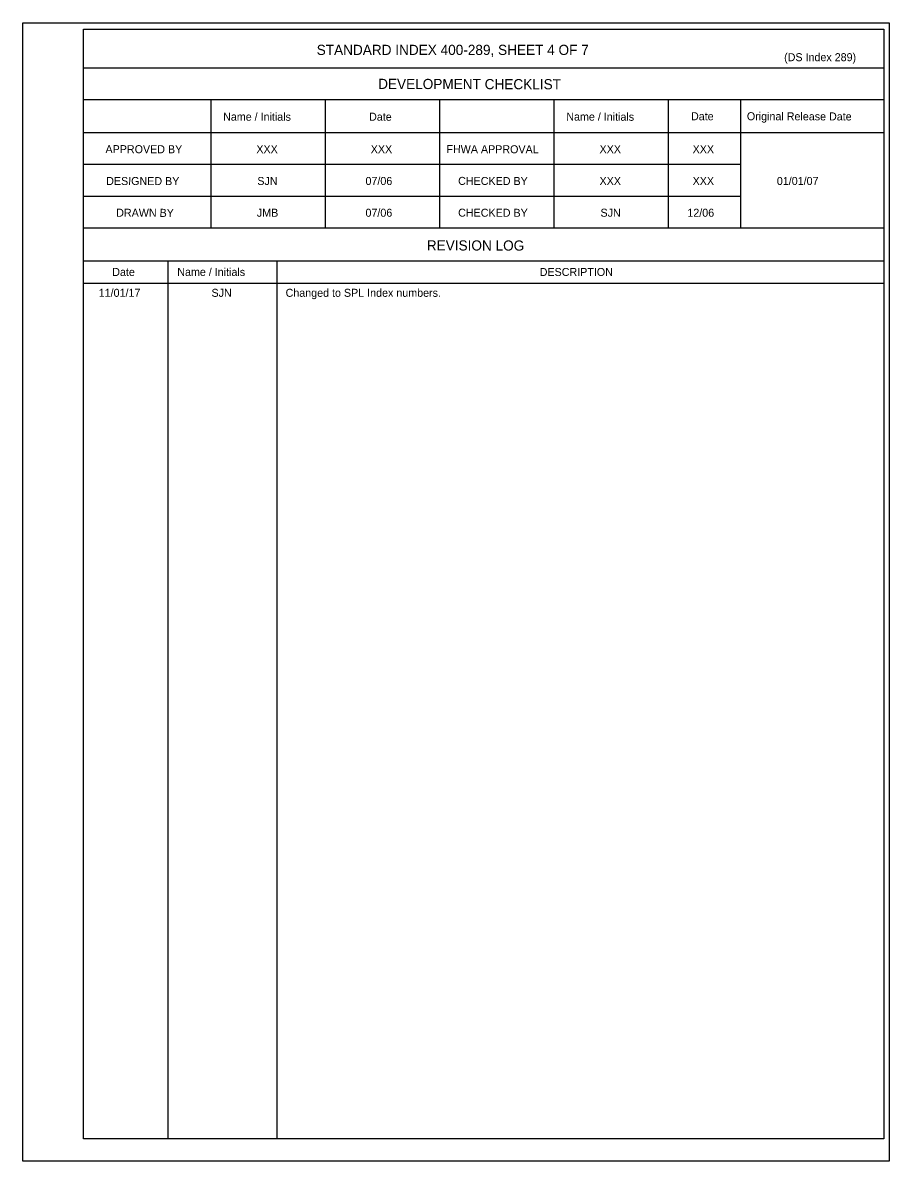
# Model space of a CAD drawing. Extents: x 6 to 221, y -2 to 90.
# Drawn here: x 155.3 to 220.8, y -1.7 to 84.3 of the extents above; entities that cross this region are included whole.
import ezdxf

# ---------------------------------------------------------------- set-up
doc = ezdxf.new("R2010")
doc.units = 0
for name, color, linetype in [('AdhocPoint_dp', 7, 'Continuous'), ('Patterning', 7, 'Continuous'), ('TextMisc', 7, 'Continuous')]:
    doc.layers.add(name, color=color, linetype=linetype)

msp = doc.modelspace()

# ---------------------------------------------------------------- linework, layer by layer
at = {"layer": 'AdhocPoint_dp'}
msp.add_line((220.772, -1.7), (220.772, -1.7), dxfattribs=at)
at = {"layer": 'Patterning'}
msp.add_line((155.333, -1.7), (155.333, -1.7), dxfattribs=at)
msp.add_lwpolyline([(155.333, 84.3), (220.772, 84.3), (220.772, -1.7), (155.333, -1.7)], close=True, dxfattribs=at)
at = {"layer": 'TextMisc'}
for p, q in [((220.364, 80.87), (159.924, 80.87)), ((220.364, 78.47), (159.924, 78.47)), ((169.524, 78.47), (169.524, 68.787)), ((178.164, 78.47), (178.164, 68.787)), ((186.804, 78.47), (186.804, 68.787)), ((195.444, 78.47), (195.444, 68.787)), ((204.084, 78.47), (204.084, 68.787)), ((209.529, 78.47), (209.529, 68.787)), ((220.364, 75.987), (159.924, 75.987)), ((209.529, 73.587), (159.924, 73.587)), ((209.529, 71.187), (159.924, 71.187)), ((220.364, 68.787), (159.924, 68.787)), ((220.364, 66.303), (159.924, 66.303)), ((166.285, 66.303), (166.285, -0.016)), ((174.512, 66.303), (174.512, -0.016)), ((220.364, 64.612), (159.924, 64.612))]:
    msp.add_line(p, q, dxfattribs=at)
msp.add_lwpolyline([(159.925, 83.812), (220.364, 83.812), (220.364, -0.016), (159.925, -0.016)], close=True, dxfattribs=at)

# ---------------------------------------------------------------- texts
at = {"layer": 'AdhocPoint_dp'}
for s, height, p in [('STANDARD INDEX 400-289, SHEET 4 OF 7', 0.768, (177.532, 81.868)), ('(DS Index 289)', 0.6048, (212.834, 81.397)), ('XXX', 0.6048, (172.974, 74.447)), ('XXX', 0.6048, (181.614, 74.447)), ('XXX', 0.6048, (198.894, 74.447)), ('XXX', 0.6048, (205.924, 74.447)), ('SJN', 0.6048, (173.047, 72.047)), ('07/06', 0.6048, (181.216, 72.047)), ('XXX', 0.6048, (198.894, 72.047)), ('XXX', 0.6048, (205.924, 72.047)), ('01/01/07', 0.6048, (212.285, 72.047)), ('JMB', 0.6048, (173.013, 69.647)), ('07/06', 0.6048, (181.216, 69.647)), ('SJN', 0.6048, (198.967, 69.647)), ('12/06', 0.6048, (205.526, 69.647)), ('DESCRIPTION', 0.6048, (194.375, 65.172)), ('11/01/17', 0.6048, (161.067, 63.598)), ('SJN', 0.6048, (169.588, 63.598)), ('Changed to SPL Index numbers.', 0.6048, (175.182, 63.598))]:
    msp.add_text(s, height=height, dxfattribs=at).set_placement(p)
for s, height, p in [('DEVELOPMENT CHECKLIST', 0.768, (182.171, 79.3)), ('Name / Initials', 0.6048, (170.462, 76.907)), ('Date', 0.6048, (181.486, 76.902)), ('Name / Initials', 0.6048, (196.382, 76.907)), ('Date', 0.6048, (205.801, 76.937)), ('Original Release Date', 0.6048, (210.02, 76.937)), ('APPROVED BY', 0.6048, (161.579, 74.452)), ('FHWA APPROVAL', 0.6048, (187.329, 74.452)), ('DESIGNED BY', 0.6048, (161.63, 72.047)), ('CHECKED BY', 0.6048, (188.214, 72.052)), ('DRAWN BY', 0.6048, (162.388, 69.647)), ('CHECKED BY', 0.6048, (188.214, 69.652)), ('REVISION LOG', 0.768, (185.847, 67.103)), ('Date', 0.6048, (162.091, 65.174)), ('Name / Initials', 0.6048, (167.001, 65.179))]:
    msp.add_text(s, height=height, rotation=359.87563, dxfattribs=at).set_placement(p)

doc.saveas('drawing.dxf')
